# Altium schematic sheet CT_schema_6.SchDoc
size 368 x 245 mm
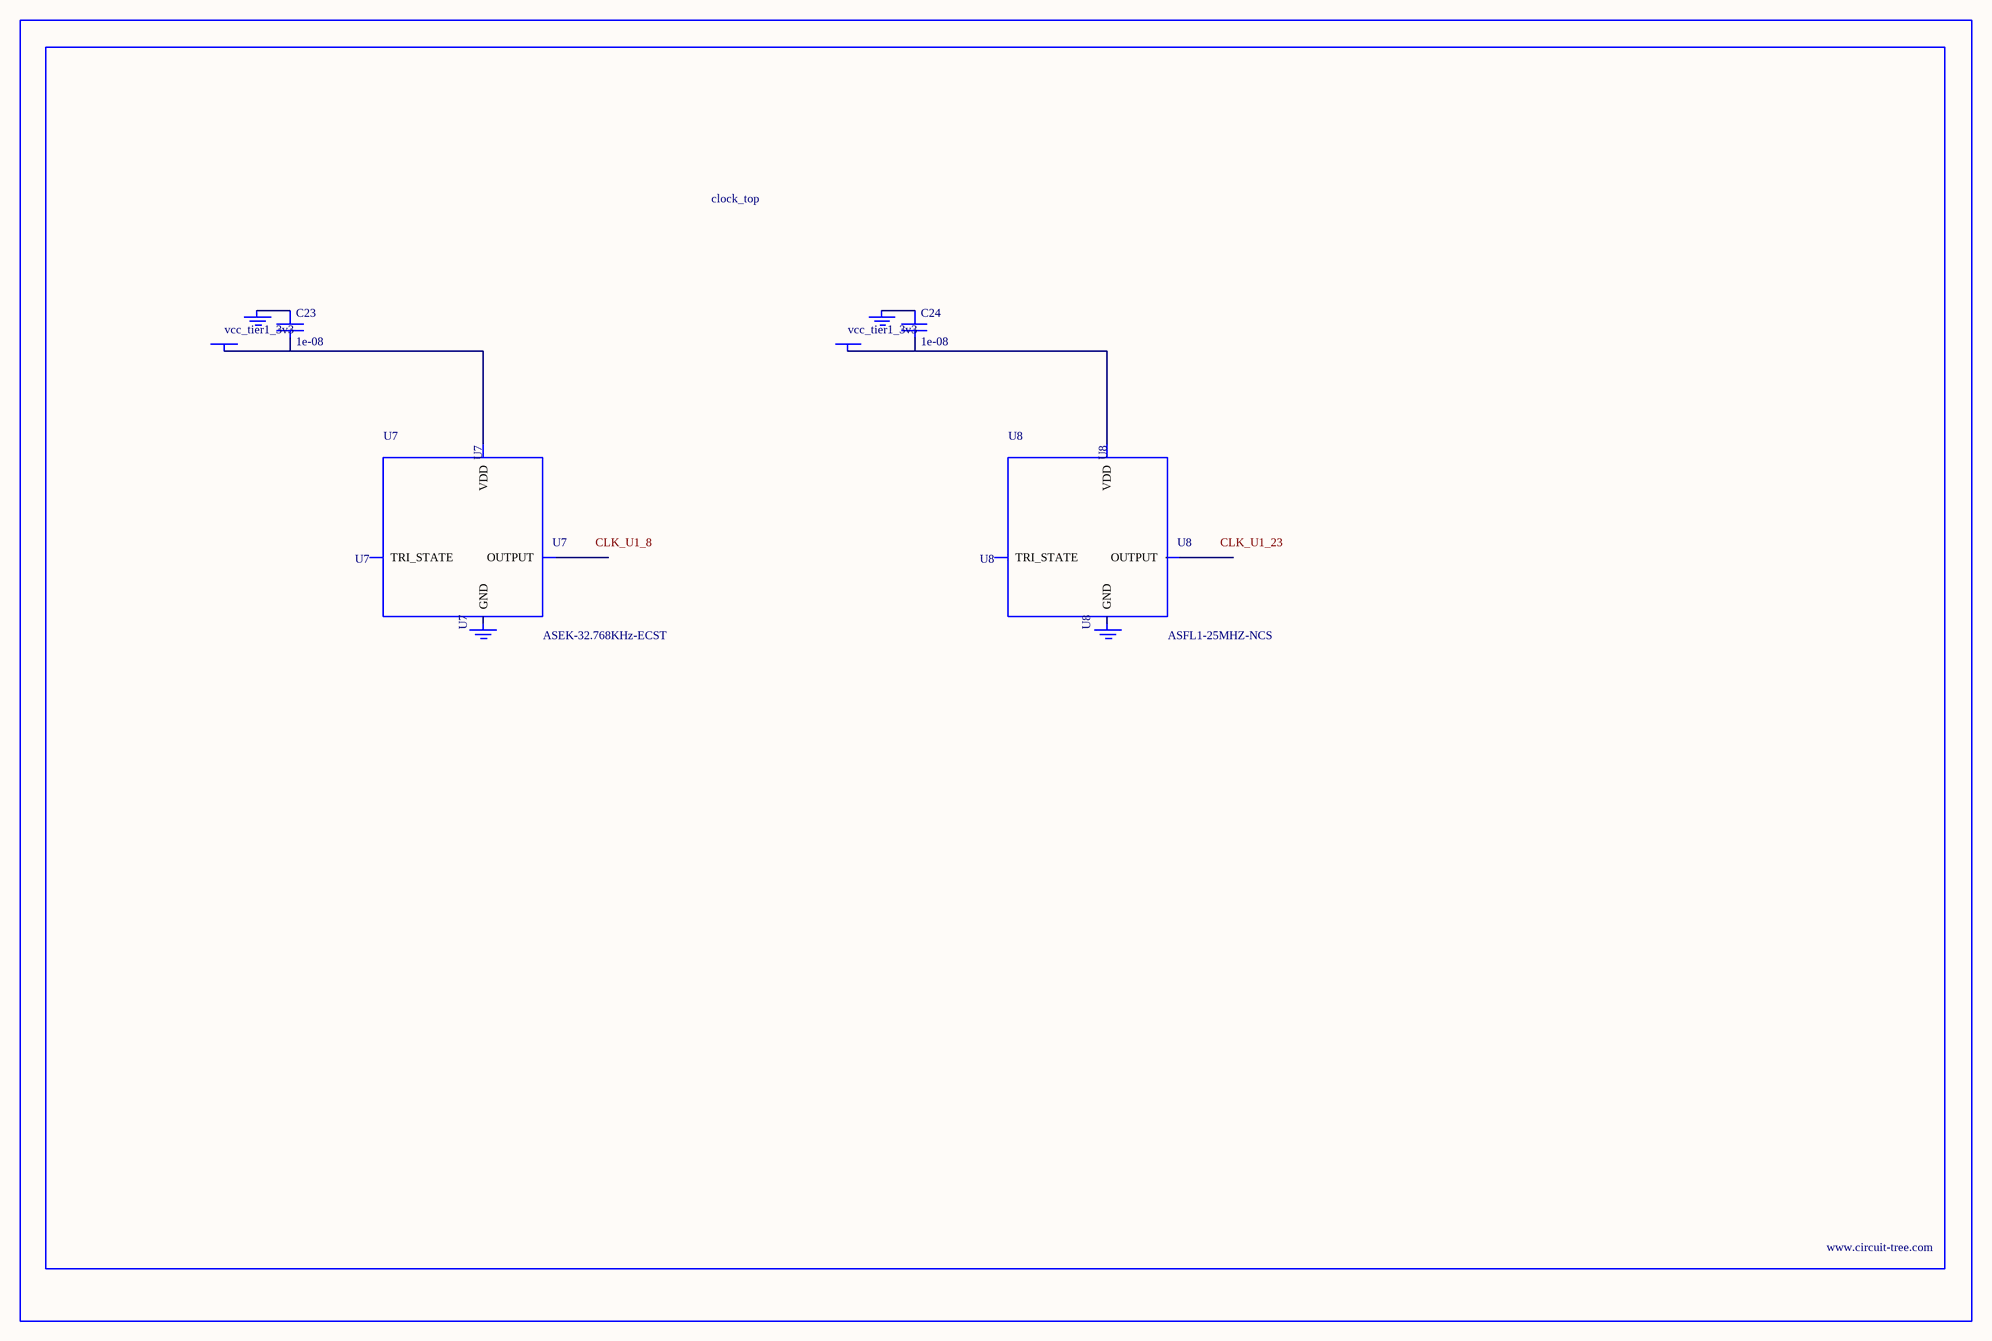
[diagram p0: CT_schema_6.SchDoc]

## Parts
BORDER5  (no value)
C23  1e-08  [C0402]
C24  1e-08  [C0402]
GND_INSTANCE_5_0  (no value)
GND_INSTANCE_5_1  (no value)
GND_INSTANCE_5_2  (no value)
GND_INSTANCE_5_3  (no value)
POWER_INSTANCE_5_0  vcc_tier1_3v3
POWER_INSTANCE_5_1  vcc_tier1_3v3
U7  ASEK-32.768KHz-ECST  [ASEK]
U8  ASFL1-25MHZ-NCS  [ASFL1]

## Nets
NetC23_1: C23.1 GND_INSTANCE_5_0.0(GND)
NetC23_2: C23.2 POWER_INSTANCE_5_0.0(PWR) U7.4(VDD)
NetC24_1: C24.1 GND_INSTANCE_5_2.0(GND)
NetC24_2: C24.2 POWER_INSTANCE_5_1.0(PWR) U8.4(VDD)

Not connected (* = marked no-connect by the designer): GND_INSTANCE_5_1 0(GND); GND_INSTANCE_5_3 0(GND); U7 1(TRI_STATE) 2(GND) 3(OUTPUT); U8 1(TRI_STATE) 2(GND) 3(OUTPUT)

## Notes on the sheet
- Labels drawn without touching a wire or pin: CLK_U1_8, CLK_U1_23

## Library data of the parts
BORDER5 = BORDER_PAGE5
C23 C24 = C0402C103K3RAC
GND_INSTANCE_5_0-GND_INSTANCE_5_3 = GND
POWER_INSTANCE_5_0 POWER_INSTANCE_5_1 = PWR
